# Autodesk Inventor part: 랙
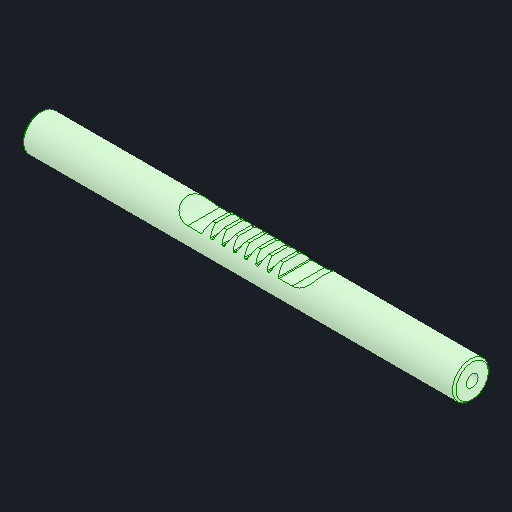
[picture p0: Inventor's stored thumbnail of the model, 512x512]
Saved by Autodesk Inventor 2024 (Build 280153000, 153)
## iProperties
Created: 2024-05
Part Number: 랙
Material: 강철, 탄소
Document SubType Name: Modeling
Designer: kh_501
Density: 7.85 g/cm^3
Appearance: 기본값
Sending System: Autodesk Inventor 2025
Preprocessor: ST-DEVELOPER v20
Author: jhkim
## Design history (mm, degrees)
node "랙1"
node "솔리드2"
node "솔리드1"
